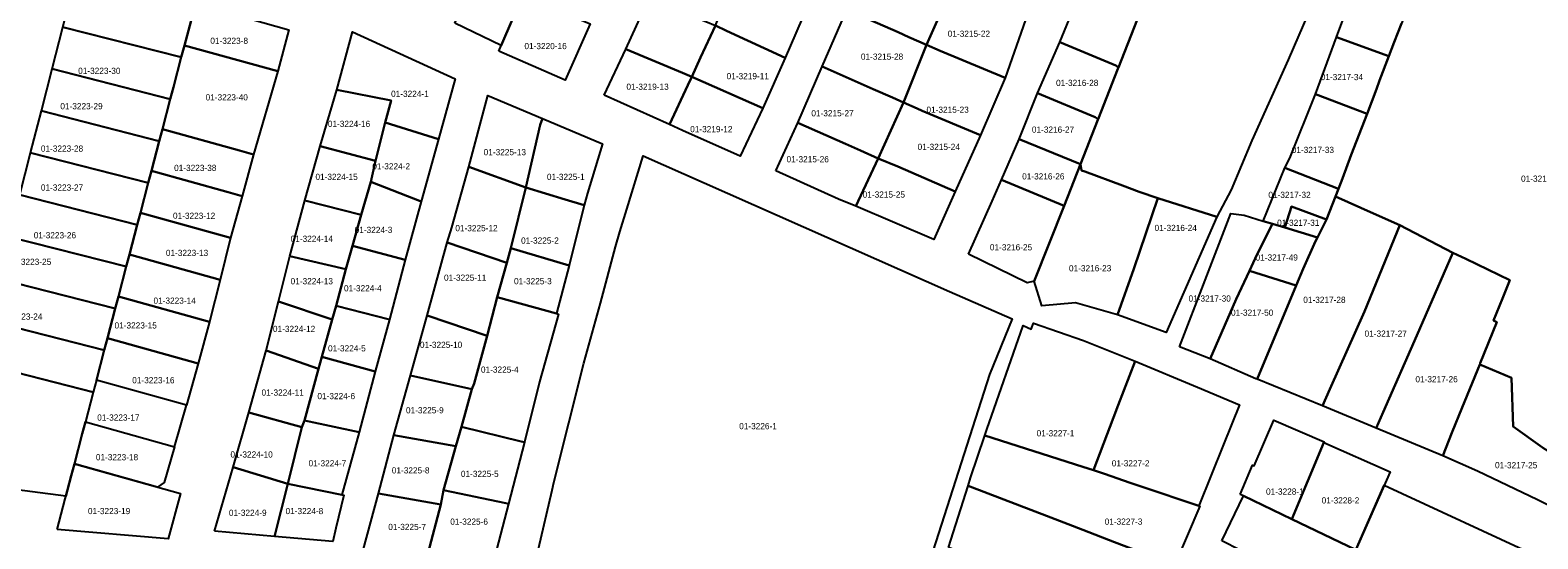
# Model space of a CAD drawing. Extents: x 419396 to 421519, y 4453567 to 4456767.
# Drawn here: x 420782.6 to 421026.3, y 4454058.3 to 4454140.5 of the extents above; entities that cross this region are included whole.
import ezdxf

# ---------------------------------------------------------------- set-up
doc = ezdxf.new("R2010")
doc.units = 0
doc.layers.add('0_KADASTRO', color=7, linetype='Continuous')

msp = doc.modelspace()

# ---------------------------------------------------------------- linework, layer by layer
at = {"layer": '0_KADASTRO'}
for p, q in [((420793.27, 4454083.93), (420792.77, 4454081.99)), ((420807.84, 4454079.87), (420793.27, 4454083.93)), ((420792.77, 4454081.99), (420791.49, 4454077.16)), ((420805.91, 4454073.14), (420807.84, 4454079.87)), ((420791.49, 4454077.16), (420805.91, 4454073.14))]:
    msp.add_line(p, q, dxfattribs=at)
for points in [[(420851.23, 4454141.66), (420856.98, 4454154.24), (420864.51, 4454151.27), (420863.72, 4454149.37), (420862.38, 4454146.15), (420862.2, 4454146.23), (420858.72, 4454138.06)], [(420914.61, 4454143.83), (420918.62, 4454152.97), (420920.97, 4454151.94), (420929.15, 4454148.37), (420930.19, 4454147.91), (420931.53, 4454147.32), (420927.47, 4454138.14), (420924.61, 4454139.41), (420922.87, 4454140.18)], [(420949.01, 4454138.58), (420955.18, 4454153.57), (420964.28, 4454149.23), (420961.52, 4454142.19), (420958.51, 4454134.5), (420958.06, 4454134.83)], [(420787.82, 4454141.02), (420789.55, 4454147.8), (420808.78, 4454142.9), (420807.51, 4454138.06), (420807, 4454136.13)], [(420893.35, 4454141.26), (420893.98, 4454142.71), (420895.44, 4454146), (420896.29, 4454147.91), (420896.85, 4454149.29), (420908.25, 4454144.39), (420904.61, 4454136.07), (420895.13, 4454140.44)], [(420927.47, 4454138.14), (420931.53, 4454147.32), (420933.7, 4454146.39), (420942.75, 4454142.49), (420943.48, 4454142.17), (420940.17, 4454132.83), (420929.71, 4454137.2)], [(420993.74, 4454139.4), (420997.2, 4454148.65), (421005.81, 4454145.67), (421004.27, 4454141.62), (421003.11, 4454138.58), (421002.25, 4454136.33)], [(420807.51, 4454138.06), (420808.78, 4454142.9), (420809.29, 4454144.83), (420824.39, 4454140.6), (420822.58, 4454133.88)], [(420858.33, 4454137.14), (420858.72, 4454138.06), (420862.2, 4454146.23), (420862.38, 4454146.15), (420873.1, 4454141.53), (420869.08, 4454132.42)], [(420878.89, 4454137.47), (420882.6, 4454145.65), (420891.8, 4454141.9), (420893.35, 4454141.26), (420890.96, 4454136.08), (420889.53, 4454132.95), (420888, 4454133.6)], [(420910.63, 4454134.62), (420914.61, 4454143.83), (420922.87, 4454140.18), (420924.61, 4454139.41), (420927.47, 4454138.14), (420923.76, 4454128.83), (420921.97, 4454129.62), (420918.86, 4454130.99)], [(420786.1, 4454134.25), (420787.82, 4454141.02), (420807, 4454136.13), (420805.73, 4454131.29), (420805.22, 4454129.36)], [(420832.14, 4454130.88), (420834.65, 4454140.24), (420851.28, 4454132.65), (420848.57, 4454122.91), (420839.96, 4454125.59), (420840.91, 4454129.17)], [(420889.53, 4454132.95), (420890.96, 4454136.08), (420893.35, 4454141.26), (420895.13, 4454140.44), (420904.61, 4454136.07), (420901.04, 4454127.9)], [(420803.95, 4454124.53), (420805.22, 4454129.36), (420805.73, 4454131.29), (420807, 4454136.13), (420807.51, 4454138.06), (420822.58, 4454133.88), (420818.68, 4454120.42), (420816.39, 4454121.06)], [(420875.38, 4454130), (420878.89, 4454137.47), (420888, 4454133.6), (420889.53, 4454132.95), (420888.91, 4454131.61), (420885.94, 4454125.25)], [(420923.76, 4454128.83), (420927.47, 4454138.14), (420929.71, 4454137.2), (420940.17, 4454132.83), (420936.2, 4454123.54), (420926.78, 4454127.47), (420925.96, 4454127.84)], [(420945.4, 4454130.32), (420949.01, 4454138.58), (420958.06, 4454134.83), (420958.51, 4454134.5), (420958.42, 4454134.29), (420955.23, 4454126.13), (420954.72, 4454126.44)], [(420990.39, 4454130.16), (420993.74, 4454139.4), (421002.25, 4454136.33), (421000.74, 4454132.36), (421000.23, 4454131), (420998.71, 4454127.01)], [(420784.37, 4454127.46), (420786.1, 4454134.25), (420805.22, 4454129.36), (420803.95, 4454124.53), (420803.44, 4454122.59)], [(420885.94, 4454125.25), (420888.91, 4454131.61), (420889.53, 4454132.95), (420901.04, 4454127.9), (420897.36, 4454120.12), (420888, 4454124.32)], [(420906.66, 4454125.52), (420910.63, 4454134.62), (420918.86, 4454130.99), (420921.97, 4454129.62), (420923.76, 4454128.83), (420919.66, 4454119.77), (420916.83, 4454121.04), (420914.4, 4454122.12)], [(420829.43, 4454121.75), (420832.14, 4454130.88), (420840.91, 4454129.17), (420839.96, 4454125.59), (420838.4, 4454119.41)], [(420942.46, 4454122.9), (420945.4, 4454130.32), (420954.72, 4454126.44), (420955.23, 4454126.13), (420955.18, 4454126.03), (420952.37, 4454118.83)], [(420985.43, 4454118.25), (420986.23, 4454119.81), (420990.39, 4454130.16), (420998.71, 4454127.01), (420996.16, 4454120.34), (420994.72, 4454116.55), (420994.08, 4454114.89)], [(420853.47, 4454118.4), (420856.36, 4454129.17), (420856.57, 4454129.94), (420865.4, 4454126.23), (420864.99, 4454125.19), (420862.7, 4454115.06)], [(420919.66, 4454119.77), (420923.76, 4454128.83), (420925.96, 4454127.84), (420926.78, 4454127.47), (420936.2, 4454123.54), (420932.13, 4454114.45), (420922.82, 4454118.5)], [(420782.64, 4454120.68), (420784.37, 4454127.46), (420803.44, 4454122.59), (420802.17, 4454117.75), (420801.66, 4454115.83)], [(420837.65, 4454115.98), (420838.4, 4454119.41), (420839.96, 4454125.59), (420848.57, 4454122.91), (420845.79, 4454112.8)], [(420862.7, 4454115.06), (420864.99, 4454125.19), (420865.4, 4454126.23), (420875.09, 4454122.15), (420872.66, 4454114.17), (420872.15, 4454112.2), (420869.05, 4454113.13)], [(420903.14, 4454117.79), (420906.66, 4454125.52), (420914.4, 4454122.12), (420916.83, 4454121.04), (420919.66, 4454119.77), (420916.05, 4454112.08), (420913.24, 4454113.21)], [(420802.17, 4454117.75), (420803.44, 4454122.59), (420803.95, 4454124.53), (420816.39, 4454121.06), (420818.68, 4454120.42), (420816.81, 4454113.67), (420814.56, 4454114.3)], [(420939.59, 4454116.31), (420942.46, 4454122.9), (420952.37, 4454118.83), (420949.71, 4454112.14)], [(420780.91, 4454113.9), (420782.64, 4454120.68), (420801.66, 4454115.83), (420800.39, 4454111), (420799.88, 4454109.06)], [(420826.99, 4454112.97), (420829.43, 4454121.75), (420838.4, 4454119.41), (420837.65, 4454115.98), (420836.08, 4454110.66)], [(420849.99, 4454106.19), (420850.74, 4454108.6), (420853.47, 4454118.4), (420862.7, 4454115.06), (420860.26, 4454105.29), (420859.62, 4454102.91)], [(420864.77, 4454056.64), (420866.98, 4454066.12), (420867.2, 4454067.38), (420872.05, 4454086.67), (420874.75, 4454096.39), (420877.22, 4454105.47), (420877.91, 4454107.92), (420879.02, 4454111.55), (420881.66, 4454120.19), (420891.55, 4454115.81), (420931.2, 4454098.26), (420941.3, 4454093.83), (420937.64, 4454084.83), (420927.6, 4454053.41), (420910.51, 4454054.28), (420885.02, 4454055.59), (420874.83, 4454056.12)], [(420916.05, 4454112.08), (420919.66, 4454119.77), (420922.82, 4454118.5), (420932.13, 4454114.45), (420928.67, 4454106.65)], [(420944.88, 4454099.95), (420949.71, 4454112.14), (420952.37, 4454118.83), (420952.53, 4454117.84), (420953.08, 4454117.64), (420959.17, 4454115.4), (420961.87, 4454114.4), (420964.89, 4454113.34), (420960.99, 4454101.94), (420958.38, 4454094.49), (420951.54, 4454096.41), (420946.14, 4454095.93)], [(420981.9, 4454109.65), (420985.43, 4454118.25), (420994.08, 4454114.89), (420993.59, 4454113.64), (420992.12, 4454109.93), (420986.46, 4454112), (420985.42, 4454108.6), (420983.4, 4454109.2)], [(420800.39, 4454111), (420801.66, 4454115.83), (420802.17, 4454117.75), (420814.56, 4454114.3), (420816.81, 4454113.67), (420814.95, 4454106.94)], [(420834.68, 4454105.66), (420836.08, 4454110.66), (420837.65, 4454115.98), (420845.79, 4454112.8), (420843.19, 4454103.4)], [(420934.24, 4454104.31), (420938.08, 4454112.87), (420939.59, 4454116.31), (420949.71, 4454112.14), (420944.88, 4454099.95), (420943.74, 4454099.65)], [(420779.18, 4454107.12), (420780.91, 4454113.9), (420799.88, 4454109.06), (420798.6, 4454104.23), (420798.1, 4454102.29)], [(420860.26, 4454105.29), (420862.7, 4454115.06), (420869.05, 4454113.13), (420872.15, 4454112.2), (420869.73, 4454102.48)], [(420958.38, 4454094.49), (420960.99, 4454101.94), (420964.89, 4454113.34), (420974.42, 4454110.33), (420966.22, 4454091.62)], [(420980.93, 4454084.11), (420987.24, 4454099.23), (420988.36, 4454101.91), (420990.35, 4454106.39), (420990.67, 4454107.01), (420992.12, 4454109.93), (420993.59, 4454113.64), (420999.72, 4454110.9), (421004, 4454108.99), (420998.27, 4454095.04), (420992.71, 4454082.47), (420991.52, 4454079.77)], [(420798.6, 4454104.23), (420799.88, 4454109.06), (420800.39, 4454111), (420814.95, 4454106.94), (420813.27, 4454100.15)], [(420824.52, 4454103.99), (420826.99, 4454112.97), (420836.08, 4454110.66), (420834.68, 4454105.66), (420833.62, 4454101.89)], [(420968.39, 4454089.32), (420976.66, 4454110.9), (420978.83, 4454110.6), (420981.9, 4454109.65), (420983.4, 4454109.2), (420980.9, 4454104.2), (420979.7, 4454101.61), (420977.56, 4454097), (420973.35, 4454087.38)], [(420985.42, 4454108.6), (420986.46, 4454112), (420992.12, 4454109.93), (420990.67, 4454107.01)], [(420979.7, 4454101.61), (420980.9, 4454104.2), (420983.4, 4454109.2), (420985.42, 4454108.6), (420990.67, 4454107.01), (420990.35, 4454106.39), (420988.36, 4454101.91), (420987.24, 4454099.23)], [(420991.52, 4454079.77), (420992.71, 4454082.47), (420998.27, 4454095.04), (421004, 4454108.99), (421012.59, 4454104.53), (421006.74, 4454091.16), (421001.32, 4454078.76), (421000.19, 4454076.17)], [(420777.45, 4454100.33), (420779.18, 4454107.12), (420798.1, 4454102.29), (420796.82, 4454097.46), (420796.32, 4454095.52)], [(420846.77, 4454094.38), (420849.99, 4454106.19), (420859.62, 4454102.91), (420858.04, 4454097.34), (420856.44, 4454091.11)], [(420796.82, 4454097.46), (420798.1, 4454102.29), (420798.6, 4454104.23), (420813.27, 4454100.15), (420811.56, 4454093.36)], [(420822.7, 4454096.62), (420824.52, 4454103.99), (420833.62, 4454101.89), (420832.06, 4454095.93), (420831.4, 4454093.73)], [(420832.06, 4454095.93), (420833.62, 4454101.89), (420834.68, 4454105.66), (420843.19, 4454103.4), (420840.63, 4454093.72)], [(420858.04, 4454097.34), (420859.62, 4454102.91), (420860.26, 4454105.29), (420869.73, 4454102.48), (420867.66, 4454094.68)], [(421000.19, 4454076.17), (421001.32, 4454078.76), (421006.74, 4454091.16), (421012.59, 4454104.53), (421014.65, 4454103.54), (421021.79, 4454100.1), (421020.59, 4454097.12), (421019.16, 4454093.58), (421019.67, 4454093.28), (421016.99, 4454086.67), (421016.91, 4454086.45), (421014.1, 4454079.52), (421012.43, 4454075.39), (421010.93, 4454071.69)], [(420973.35, 4454087.38), (420977.56, 4454097), (420979.7, 4454101.61), (420987.24, 4454099.23), (420980.93, 4454084.11), (420980.72, 4454084.13)], [(420775.73, 4454093.56), (420777.45, 4454100.33), (420796.32, 4454095.52), (420795.04, 4454090.69), (420794.54, 4454088.75)], [(420795.04, 4454090.69), (420796.32, 4454095.52), (420796.82, 4454097.46), (420811.56, 4454093.36), (420809.72, 4454086.61)], [(420820.7, 4454088.7), (420822.7, 4454096.62), (420831.4, 4454093.73), (420829.73, 4454087.68), (420829.16, 4454085.75)], [(420852.28, 4454076.37), (420853.99, 4454082.47), (420854.33, 4454083.38), (420856.44, 4454091.11), (420858.04, 4454097.34), (420867.66, 4454094.68), (420867.97, 4454094.6), (420864.93, 4454083.64), (420862.47, 4454073.88), (420861.96, 4454074)], [(420774, 4454086.77), (420775.73, 4454093.56), (420794.54, 4454088.75), (420793.27, 4454083.93), (420792.77, 4454081.99)], [(420829.73, 4454087.68), (420831.4, 4454093.73), (420832.06, 4454095.93), (420840.63, 4454093.72), (420838.35, 4454085.3)], [(420844.07, 4454084.7), (420846.77, 4454094.38), (420856.44, 4454091.11), (420854.33, 4454083.38), (420853.99, 4454082.47)], [(420936.9, 4454074.98), (420937.23, 4454075.96), (420943.11, 4454092.74), (420944.42, 4454092.15), (420944.77, 4454093.14), (420952.86, 4454090.32), (420961.23, 4454087.01), (420958.44, 4454079.87), (420957.69, 4454077.89), (420954.47, 4454069.35), (420952.77, 4454069.93)], [(420793.27, 4454083.93), (420794.54, 4454088.75), (420795.04, 4454090.69), (420809.72, 4454086.61), (420807.84, 4454079.87)], [(420817.9, 4454078.72), (420820.7, 4454088.7), (420829.16, 4454085.75), (420826.92, 4454077.41), (420826.5, 4454076.32)], [(420769.87, 4454070.56), (420770.54, 4454073.21), (420772.27, 4454079.99), (420774, 4454086.77), (420792.77, 4454081.99), (420791.49, 4454077.16), (420790.98, 4454075.22), (420789.71, 4454070.39), (420789.2, 4454068.46), (420788.33, 4454065.14), (420772.09, 4454067.28)], [(420826.92, 4454077.41), (420829.16, 4454085.75), (420829.73, 4454087.68), (420838.35, 4454085.3), (420835.73, 4454075.5)], [(420954.47, 4454069.35), (420957.69, 4454077.89), (420958.44, 4454079.87), (420961.23, 4454087.01), (420971.28, 4454082.8), (420978.09, 4454079.92), (420975.51, 4454073.5), (420971.51, 4454063.58), (420969.43, 4454064.3), (420964.29, 4454066.03), (420960.41, 4454067.34), (420956.25, 4454068.75)], [(421010.93, 4454071.69), (421012.43, 4454075.39), (421014.1, 4454079.52), (421016.91, 4454086.45), (421022.07, 4454084.3), (421022.32, 4454076.45), (421027.05, 4454073.01), (421029.49, 4454071.5), (421030.24, 4454070.92), (421036.02, 4454066.93), (421032.36, 4454061.48), (421026.25, 4454064.56), (421016.55, 4454069.2)], [(420841.38, 4454075.04), (420844.07, 4454084.7), (420853.99, 4454082.47), (420852.28, 4454076.37), (420851.37, 4454073.23)], [(420789.71, 4454070.39), (420790.98, 4454075.22), (420791.49, 4454077.16), (420805.91, 4454073.14), (420804.24, 4454067.35), (420803.17, 4454066.64)], [(420815.37, 4454069.84), (420817.9, 4454078.72), (420826.5, 4454076.32), (420824.22, 4454067.18)], [(420824.22, 4454067.18), (420826.5, 4454076.32), (420826.92, 4454077.41), (420835.73, 4454075.5), (420832.96, 4454065.4)], [(420978.2, 4454065.44), (420980.2, 4454070.16), (420980.47, 4454070.05), (420983.62, 4454077.43), (420991.76, 4454073.96), (420991.71, 4454073.83), (420986.54, 4454061.47), (420978.75, 4454065.22)], [(420838.88, 4454065.61), (420841.38, 4454075.04), (420851.37, 4454073.23), (420849.41, 4454066.14), (420848.93, 4454063.83)], [(420849.41, 4454066.14), (420851.37, 4454073.23), (420852.28, 4454076.37), (420861.96, 4454074), (420862.47, 4454073.88), (420859.89, 4454063.93), (420859.49, 4454064.03)], [(420934.19, 4454066.86), (420934.59, 4454068.11), (420936.9, 4454074.98), (420952.77, 4454069.93), (420954.47, 4454069.35), (420956.25, 4454068.75), (420960.41, 4454067.34), (420964.29, 4454066.03), (420969.43, 4454064.3), (420971.51, 4454063.58), (420971.64, 4454063.54), (420967.58, 4454053.97), (420966.24, 4454054.5), (420965.5, 4454054.79), (420957.86, 4454057.72), (420952.73, 4454059.71), (420950.4, 4454060.61), (420947.59, 4454061.69)], [(420986.54, 4454061.47), (420991.71, 4454073.83), (421002.43, 4454069.1), (420996.88, 4454056.51)], [(420786.92, 4454059.75), (420789.2, 4454068.46), (420789.71, 4454070.39), (420806.87, 4454065.61), (420804.86, 4454058.29)], [(420812.38, 4454059.52), (420815.37, 4454069.84), (420824.22, 4454067.18), (420822.04, 4454058.66)], [(420822.04, 4454058.66), (420824.22, 4454067.18), (420832.96, 4454065.4), (420833.26, 4454065.32), (420831.99, 4454059.97), (420831.49, 4454057.82)], [(420931.01, 4454056.88), (420934.19, 4454066.86), (420947.59, 4454061.69), (420950.4, 4454060.61), (420952.73, 4454059.71), (420957.86, 4454057.72), (420965.5, 4454054.79), (420966.24, 4454054.5), (420962.29, 4454045.38), (420962, 4454044.71)], [(420996.88, 4454056.51), (421001.47, 4454066.93), (421026.83, 4454055.2), (421022.58, 4454048.19), (421020.24, 4454049.42), (421020.23, 4454048.89), (421015.04, 4454051.62), (421012.79, 4454047.47), (421005.83, 4454051.42)], [(420836.41, 4454056.44), (420838.88, 4454065.61), (420848.93, 4454063.83), (420846.83, 4454055.85)], [(420846.83, 4454055.85), (420848.93, 4454063.83), (420849.41, 4454066.14), (420859.49, 4454064.03), (420859.89, 4454063.93), (420857.64, 4454055.24)], [(420975.21, 4454057.96), (420978.75, 4454065.22), (420986.54, 4454061.47), (420996.88, 4454056.51), (420992.99, 4454048.9)]]:
    msp.add_lwpolyline(points, close=True, dxfattribs=at)
for points in [[(420989.23, 4454143.3), (420985.94, 4454135.73), (420980.07, 4454122.66), (420976.73, 4454114.69), (420974.42, 4454110.33), (420964.89, 4454113.34), (420961.87, 4454114.4), (420959.17, 4454115.4), (420953.08, 4454117.64), (420952.53, 4454117.84), (420952.37, 4454118.83), (420955.18, 4454126.03), (420955.23, 4454126.13), (420958.42, 4454134.29), (420958.51, 4454134.5), (420961.52, 4454142.19)], [(421027.05, 4454073.01), (421022.32, 4454076.45), (421022.07, 4454084.3), (421016.91, 4454086.45), (421016.99, 4454086.67), (421019.67, 4454093.28), (421019.16, 4454093.58), (421020.59, 4454097.12), (421021.79, 4454100.1), (421014.65, 4454103.54), (421012.59, 4454104.53), (421004, 4454108.99), (420999.72, 4454110.9), (420993.59, 4454113.64), (420994.08, 4454114.89), (420994.72, 4454116.55), (420996.16, 4454120.34), (420998.71, 4454127.01), (421000.23, 4454131), (421000.74, 4454132.36), (421002.25, 4454136.33), (421003.11, 4454138.58), (421004.27, 4454141.62)]]:
    msp.add_lwpolyline(points, dxfattribs=at)

# ---------------------------------------------------------------- texts
for s, p in [('01-3215-22', (420930.91, 4454139.45)), ('01-3223-8', (420811.69, 4454138.31)), ('01-3220-16', (420862.47, 4454137.45)), ('01-3215-28', (420916.87, 4454135.74)), ('01-3223-30', (420790.32, 4454133.45)), ('01-3219-11', (420895.16, 4454132.59)), ('01-3216-28', (420948.42, 4454131.5)), ('01-3217-34', (420991.21, 4454132.44)), ('01-3223-40', (420810.92, 4454129.16)), ('01-3224-1', (420840.91, 4454129.73)), ('01-3219-13', (420878.96, 4454130.88)), ('01-3223-29', (420787.44, 4454127.73)), ('01-3215-23', (420927.47, 4454127.16)), ('01-3224-16', (420830.69, 4454124.87)), ('01-3215-27', (420908.86, 4454126.59)), ('01-3219-12', (420889.27, 4454124.02)), ('01-3216-27', (420944.51, 4454123.94)), ('01-3223-28', (420784.29, 4454120.87)), ('01-3225-13', (420855.88, 4454120.3)), ('01-3215-24', (420926.04, 4454121.15)), ('01-3217-33', (420986.52, 4454120.66)), ('01-3223-38', (420805.83, 4454117.75)), ('01-3224-2', (420837.88, 4454118.01)), ('01-3215-26', (420904.85, 4454119.15)), ('01-3223-27', (420784.29, 4454114.58)), ('01-3224-15', (420828.68, 4454116.3)), ('01-3225-1', (420866.11, 4454116.3)), ('01-3216-26', (420942.94, 4454116.38)), ('01-3217-24', (421023.6, 4454116.01)), ('01-3215-25', (420917.16, 4454113.44)), ('01-3217-32', (420982.75, 4454113.39)), ('01-3223-12', (420805.65, 4454110.01)), ('01-3224-3', (420835.02, 4454107.72)), ('01-3225-12', (420851.3, 4454108.01)), ('01-3216-24', (420964.35, 4454108.04)), ('01-3217-31', (420984.16, 4454108.88)), ('01-3223-26', (420783.14, 4454106.86)), ('01-3224-14', (420824.67, 4454106.29)), ('01-3225-2', (420861.93, 4454106)), ('01-3216-25', (420937.72, 4454104.91)), ('01-3223-25', (420779.13, 4454102.57)), ('01-3223-13', (420804.5, 4454104)), ('01-3217-49', (420980.68, 4454103.26)), ('01-3225-11', (420849.47, 4454100)), ('01-3216-23', (420950.51, 4454101.52)), ('01-3224-13', (420824.67, 4454099.43)), ('01-3224-4', (420833.3, 4454098.29)), ('01-3225-3', (420860.79, 4454099.43)), ('01-3223-14', (420802.5, 4454096.28)), ('01-3217-30', (420969.84, 4454096.63)), ('01-3217-28', (420988.39, 4454096.42)), ('01-3223-24', (420777.7, 4454093.71)), ('01-3217-50', (420976.71, 4454094.34)), ('01-3223-15', (420796.2, 4454092.28)), ('01-3224-12', (420821.81, 4454091.71)), ('01-3217-27', (420998.3, 4454090.95)), ('01-3224-5', (420830.72, 4454088.57)), ('01-3225-10', (420845.58, 4454089.14)), ('01-3223-16', (420799.06, 4454083.42)), ('01-3225-4', (420855.44, 4454085.13)), ('01-3217-26', (421006.52, 4454083.58)), ('01-3224-11', (420819.97, 4454081.42)), ('01-3224-6', (420829, 4454080.85)), ('01-3225-9', (420843.32, 4454078.56)), ('01-3223-17', (420793.4, 4454077.38)), ('01-3226-1', (420897.19, 4454075.99)), ('01-3227-1', (420945.28, 4454074.84)), ('01-3223-18', (420793.18, 4454070.97)), ('01-3224-10', (420814.94, 4454071.41)), ('01-3224-7', (420827.57, 4454069.98)), ('01-3225-8', (420841.03, 4454068.84)), ('01-3225-5', (420852.2, 4454068.27)), ('01-3227-2', (420957.43, 4454069.98)), ('01-3217-25', (421019.39, 4454069.68)), ('01-3228-1', (420982.37, 4454065.41)), ('01-3228-2', (420991.36, 4454063.98)), ('01-3223-19', (420791.9, 4454062.26)), ('01-3224-9', (420814.69, 4454061.98)), ('01-3224-8', (420823.85, 4454062.26)), ('01-3225-7', (420840.46, 4454059.69)), ('01-3225-6', (420850.48, 4454060.55)), ('01-3227-3', (420956.28, 4454060.55))]:
    msp.add_text(s, height=1, dxfattribs=at).set_placement(p)

doc.saveas('drawing.dxf')
